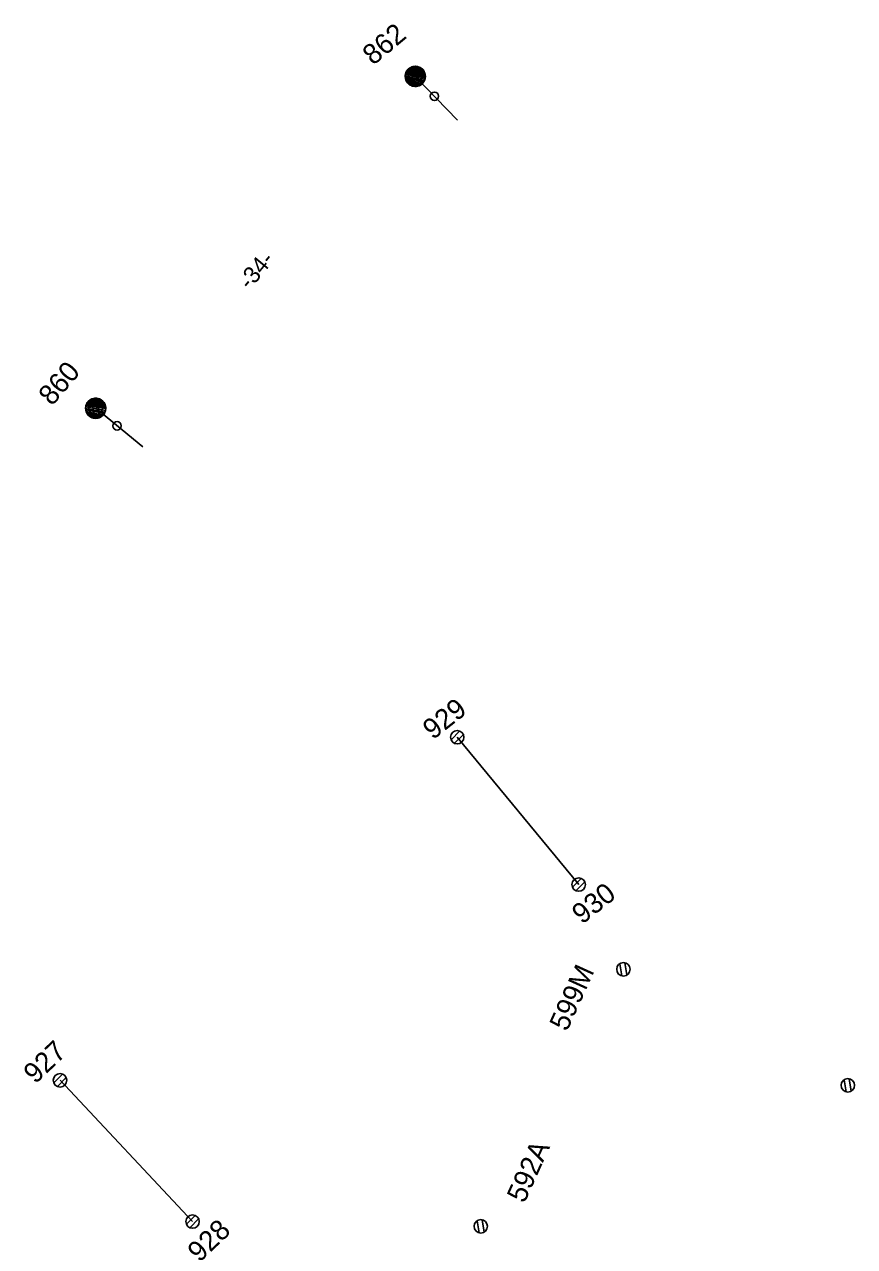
# Model space of a CAD drawing. Extents: x -595867 to -593796, y -1159595 to -1157495.
# Drawn here: x -594613.7 to -594552, y -1157776.6 to -1157685.7 of the extents above; entities that cross this region are included whole.
import ezdxf

# ---------------------------------------------------------------- set-up
doc = ezdxf.new("R2010")
doc.units = 0
for name, color, linetype in [('BVK_kanalizace_destova_nova', 7, 'Continuous'), ('BVK_kanalizace_jednotna_nova', 7, 'Continuous'), ('Teplarny Horkovod', 7, 'Continuous')]:
    doc.layers.add(name, color=color, linetype=linetype)

# ---------------------------------------------------------------- blocks, each defined once
blk = doc.blocks.new('st_tecka')
blk.add_circle((0, 0), 0.00314)
blk = doc.blocks.new('st_1t')
for points in [[(-0.00742, 0.00071), (0.00284, 0.0069), (0.00359, 0.00656), (-0.00747, -0.00023)], [(-0.00747, -0.00023), (0.00359, 0.00656), (0.00442, 0.00605), (-0.00743, -0.00101)], [(-0.00743, -0.00101), (0.00442, 0.00605), (0.00522, 0.0054), (-0.00722, -0.0019)], [(-0.00729, 0.00159), (0.00185, 0.00722), (0.00284, 0.0069), (-0.00742, 0.00071)], [(-0.00711, 0.00221), (0.00057, 0.00744), (0.00185, 0.00722), (-0.00729, 0.00159)], [(-0.00722, -0.0019), (0.00522, 0.0054), (0.00588, 0.00461), (-0.00688, -0.00302)], [(-0.00689, 0.00294), (-0.00011, 0.00749), (0.00057, 0.00744), (-0.00711, 0.00221)], [(-0.00669, 0.00331), (-0.00149, 0.00733), (-0.00011, 0.00749), (-0.00689, 0.00294)], [(-0.00688, -0.00302), (0.00588, 0.00461), (0.00666, 0.00341), (-0.00639, -0.00386)], [(-0.00627, 0.00403), (-0.00222, 0.00714), (-0.00149, 0.00733), (-0.00669, 0.00331)], [(-0.00639, -0.00386), (0.00666, 0.00341), (0.00712, 0.00224), (-0.00567, -0.00488)], [(-0.00579, 0.00472), (-0.00315, 0.00675), (-0.00222, 0.00714), (-0.00627, 0.00403)], [(-0.00526, 0.00533), (-0.00413, 0.00624), (-0.00315, 0.00675), (-0.00579, 0.00472)], [(-0.00567, -0.00488), (0.00712, 0.00224), (0.00742, 0.00112), (-0.00488, -0.00564)], [(-0.00488, -0.00564), (0.00742, 0.00112), (0.00748, -0.00042), (-0.00405, -0.00629)], [(-0.00405, -0.00629), (0.00748, -0.00042), (0.00729, -0.00175), (-0.00317, -0.00679)], [(-0.00317, -0.00679), (0.00729, -0.00175), (0.00698, -0.00275), (-0.00206, -0.00718)], [(-0.00206, -0.00718), (0.00698, -0.00275), (0.00651, -0.0037), (-0.00114, -0.0074)], [(-0.00114, -0.0074), (0.00651, -0.0037), (0.00592, -0.00458), (-0.00048, -0.00747)], [(-0.00048, -0.00747), (0.00592, -0.00458), (0.00536, -0.00524), (0.00037, -0.00747)], [(0.00037, -0.00747), (0.00536, -0.00524), (0.00449, -0.00597), (0.00138, -0.00739)], [(0.00138, -0.00739), (0.00449, -0.00597), (0.00384, -0.00644), (0.0025, -0.00702)], [(0.0025, -0.00702), (0.00384, -0.00644), (0.00295, -0.00692), (0.00293, -0.00693)]]:
    blk.add_lwpolyline(points, close=True)
blk.add_circle((0, 0), 0.0075)
blk = doc.blocks.new('st1k_1t')
blk.add_line((0, 0), (0.04531, 0))
blk.add_blockref('st_1t', (0, 0))
at = {"rotation": 90}
blk.add_blockref('st_tecka', (0.02054, 0), dxfattribs=at)
blk = doc.blocks.new('C725')
at = {"layer": 'Teplarny Horkovod'}
for p, q in [((-0.461, -0.184), (0.185, 0.462)), ((-0.201, -0.454), (0.454, 0.201))]:
    blk.add_line(p, q, dxfattribs=at)
blk.add_circle((0, 0), 0.5, dxfattribs=at)

msp = doc.modelspace()

# ---------------------------------------------------------------- linework, layer by layer
at = {"layer": 'BVK_kanalizace_jednotna_nova'}
for p, q in [((-594584.743, -1157690.083), (-594584.903, -1157689.184)), ((-594584.373, -1157690.025), (-594584.535, -1157689.113)), ((-594608.513, -1157714.773), (-594608.673, -1157713.874)), ((-594608.143, -1157714.715), (-594608.305, -1157713.803)), ((-594568.893, -1157756.445), (-594569.055, -1157755.533)), ((-594569.263, -1157756.503), (-594569.423, -1157755.604)), ((-594552.573, -1157765.133), (-594552.733, -1157764.234)), ((-594552.203, -1157765.075), (-594552.365, -1157764.163)), ((-594579.503, -1157775.565), (-594579.665, -1157774.653)), ((-594579.873, -1157775.623), (-594580.033, -1157774.724))]:
    msp.add_line(p, q, dxfattribs=at)
for centre in [(-594584.63, -1157689.6), (-594584.63, -1157689.6), (-594608.4, -1157714.29), (-594608.4, -1157714.29), (-594569.15, -1157756.02), (-594569.15, -1157756.02), (-594552.46, -1157764.65), (-594552.46, -1157764.65), (-594579.76, -1157775.14), (-594579.76, -1157775.14)]:
    msp.add_circle(centre, 0.5, dxfattribs=at)
at = {"layer": 'Teplarny Horkovod'}
for p, q in [((-594581.51, -1157738.756), (-594572.477, -1157749.721)), ((-594611.049, -1157764.279), (-594601.196, -1157774.788))]:
    msp.add_line(p, q, dxfattribs=at)

# ---------------------------------------------------------------- block references
at = {"layer": 'BVK_kanalizace_destova_nova'}
for p, xscale, yscale, rotation in [((-594584.63, -1157689.6), 100, 100, -46.17044592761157), ((-594608.4, -1157714.29), 99.99999999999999, 100.00000000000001, -39.38412760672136)]:
    msp.add_blockref('st1k_1t', p, dxfattribs=dict(at, xscale=xscale, yscale=yscale, rotation=rotation))
at = {"layer": 'Teplarny Horkovod'}
for p in [(-594581.51, -1157738.756), (-594572.477, -1157749.721), (-594611.049, -1157764.279), (-594601.196, -1157774.788)]:
    msp.add_blockref('C725', p, dxfattribs=at)

# ---------------------------------------------------------------- texts
at = {"layer": 'BVK_kanalizace_destova_nova'}
for s, height, rotation, p in [('862', 1.5, 39.7378, (-594587.761, -1157688.826)), ('-34-', 1.25, 50.44544, (-594596.952, -1157705.536)), ('860', 1.5, 49.57156, (-594611.645, -1157714.17))]:
    msp.add_text(s, height=height, rotation=rotation, dxfattribs=at).set_placement(p)
at = {"layer": 'BVK_kanalizace_jednotna_nova'}
for s, p in [('599M', (-594573.351, -1157760.702)), ('592A', (-594576.519, -1157773.479))]:
    msp.add_text(s, height=1.5, rotation=65.59844, dxfattribs=at).set_placement(p)
at = {"layer": 'Teplarny Horkovod'}
for s, rotation, p in [('929', 38.18843, (-594583.321, -1157738.99)), ('930', 38.18843, (-594572.226, -1157752.718)), ('927', 43.54065, (-594612.893, -1157764.599)), ('928', 43.54065, (-594600.69, -1157777.876))]:
    msp.add_text(s, height=1.5, rotation=rotation, dxfattribs=at).set_placement(p)

doc.saveas('drawing.dxf')
